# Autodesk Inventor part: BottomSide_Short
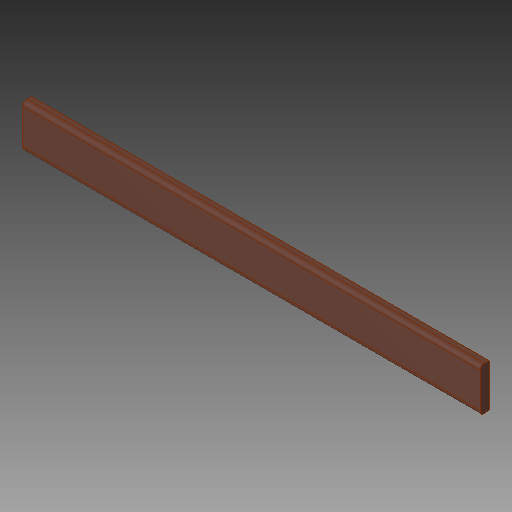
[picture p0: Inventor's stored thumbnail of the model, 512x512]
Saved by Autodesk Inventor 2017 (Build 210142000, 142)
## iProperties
Created: 2017-05
Part Number: BottomSide_Short
Material: Generic
Document SubType Name: Modeling
Designer: Savy
Density: 1 g/cm^3
Appearance: Default
Author: Savy
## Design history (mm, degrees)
feature "SOLID1"
body "Solid1"
